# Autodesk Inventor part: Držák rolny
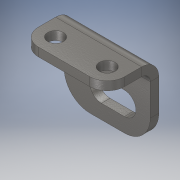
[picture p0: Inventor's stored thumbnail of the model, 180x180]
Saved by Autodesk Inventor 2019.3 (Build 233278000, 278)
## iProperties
Created: 2019-02
Part Number: Držák rolny
Material: Ocel, měkká, svařovaná
Document SubType Name: Plech
Designer: B-hon
Density: 7.85 g/cm^3
Sheet Metal Rule: Výchozí_mm
Appearance: Pozinkovaná
Author: B-hon
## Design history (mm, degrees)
node "Plocha1"
  sketch "Náčrt1"
    geometry: L1 (-9, 0)-(-30, 0); L2 (-30, 0)-(-30, 26); L3 (-30, 26)-(0, 26); L4 (0, 26)-(0, 9); L5 (-17, 9)-(-9, 9); L6 (-17, 5)-(-9, 5); L7 (-9, 13)-(-17, 13); L8 (-50.597, 35.548)-(1, 35.548); L9 (1, 35.548)-(1, 21.352); L10 (1, 21.352)-(-50.597, 21.352); L11 (-50.597, 21.352)-(-50.597, 35.548); C1 r 14 at (-9, 9); A1 r 4 centre (-17, 9) between (-17, 13) and (-17, 5); A2 r 4 centre (-9, 9) between (-9, 5) and (-9, 13); A3 r 9 centre (-9, 9) between (-9, 0) and (0, 9); 2 further points
    constraints: 24 end point, 6 point on circle, 6 tangent, 5 parallel, 4 centre point, 3 horizontal, 2 perpendicular, 2 point on line, 1 coincident, 1 midpoint
    dimensions: "d0" = 30 distance of L2.end L3.end; "d1" = 26 distance of L1.end L2.end; "d2" = 8 diameter of A2; "d4" = 9 distance from line of L4 L5.end; "d5" = 8 distance of L6.start L6.end; "d6" = 9 radius of A3 (derived); "d7" = 28 diameter of C1; "d8" = 4 distance edge to line of C1 L9; "d9" = 9 distance from line of L1 point (-13, 9)
node "Obruba1"
fillet "Zaoblení1" dims "d31" = 6
fillet "Zaoblení2" dims "d32" = 9
sketch "Náčrt4"
  geometry: A1 r 6 centre (6, -6) between (0, -6) and (6, -12) reference; A2 r 6 centre (24, -6) between (24, -12) and (30, -6) reference; 3 further points
  constraints: 2 coincident
hole "Díra2" sketch "Náčrt4" at (6, -6), (24, -6) diameter "d33" = 5.5; stored, may be unused: countersink angle "d37" = 90 deg, drill point angle "d39" = 0 deg; dims "d34" = 6, "d35" = 9.5, "d36" = 2, "d38" = 3 (= Tloušťka)
node "Těleso1"
feature "Deska1" dims "d10" = 3 (= Tloušťka)
sketch "Náčrt2"
  geometry: L1 through (-15, 0) direction (1, 0); L2 through (0, 9) direction (0, 1); L3 (0, 18)-(-30, 18); L4 (-30, 18)-(-30, 0)
  constraints: 6 end point, 1 horizontal, 1 perpendicular, 1 vertical
feature "Deska2" dims "d10" = 3 (= Tloušťka), "d11" = 3 (= ŠířkaVýštipu), "d12" = 1.5 (= HloubkaVýštipu), "d13" = 6 (= MinimálníZbytek), "d14" = 3 (= PřechodovýPoloměr), "d15" = 18, "d16" = 90 deg, "d17" = 3 (= PoloměrOhybu), "d18" = 12 (= VelikostRohovéhoVýštipu), "d19" = 3 (= VelikostMezery), "d20" = 3 (= VelikostJacobihoPoloměru), "MezeraVystřižení" = 0.01
feature "Ohyb1" dims "d10" = 3 (= Tloušťka), "d11" = 3 (= ŠířkaVýštipu), "d12" = 1.5 (= HloubkaVýštipu), "d13" = 6 (= MinimálníZbytek), "d14" = 3 (= PřechodovýPoloměr), "d15" = 18, "d16" = 90 deg, "d17" = 3 (= PoloměrOhybu), "MezeraVystřižení" = 0.01
feature "Roh1" dims "d15" = 18, "d16" = 90 deg, "d18" = 12 (= VelikostRohovéhoVýštipu), "d19" = 3 (= VelikostMezery), "d20" = 3 (= VelikostJacobihoPoloměru)
other parameters: "Tloušťka" = 3 (derived), "KSoučinitel" = 4.4, "PoloměrOhybu" = 3 (= Tloušťka), "ŠířkaVýštipu" = 3 (= Tloušťka), "HloubkaVýštipu" = 1.5 (= 0.5 x Tloušťka), "VelikostRohovéhoVýštipu" = 12 (= 4 x Tloušťka), "MinimálníZbytek" = 6 (= 2 x Tloušťka), "PřechodovýPoloměr" = 3 (= PoloměrOhybu), "VelikostJacobihoPoloměru" = 3 (= PoloměrOhybu), "VelikostMezery" = 3 (= Tloušťka)
